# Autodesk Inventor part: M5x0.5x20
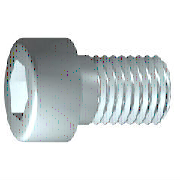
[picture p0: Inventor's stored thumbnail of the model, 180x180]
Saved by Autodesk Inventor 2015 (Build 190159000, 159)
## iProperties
IsCustomPart: 0
Created: 2009-02
Part Number: M5x0.5x20
Material: Steel, Mild
Description: 6각머리 태핑 나사
Document SubType Name: Modeling
Standard: KS B 1003
Designer: SeoGD™
Standards Organization: KS
Language: ko-KR
Size Designation: M 5 x 20
Categories: <MemberInstance><Categories><Category DisplayName="조임쇠" InternalName="e4da775c-781d-43d5-af7c-5136215cf5a6" Mnemonic="FSTN"><Category DisplayName="볼트" InternalN
Density: 7.86 g/cm^3
Appearance: Metal-Steel
Mass: 4.9629 g
Surface Area: 5.88237 cm^2
Volume: 0.631412 cm^3
Author: SeoGD™
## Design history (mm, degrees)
sketch "스케치1"
  geometry: L1 (-1.167, 0)-(20, 0); L2 (20, 0)-(20, 2.5); L3 (20, 2.5)-(2, 2.5); L4 (2, 2.5)-(1.509, 2.5); L5 (1.509, 2.5)-(0, 2.5); L6 (0, 2.5)-(0, 4.25); L7 (0, 4.25)-(-5, 4.25); L8 (-5, 4.25)-(-5, 2.309); L9 (-5, 2.309)-(-2.5, 2.309); L10 (-2.5, 2.309)-(-1.167, 0); L11 (-10, 0)-(25, 0) reference; L12 (0, -0.85)-(0, 5.1) reference; L13 (2, 2.5)-(0, 2.5)
  constraints: 22 end point, 6 parallel, 2 collinear, 2 perpendicular, 1 horizontal, 1 point on line
  dimensions: "d1" = 18 distance from line of L3.end L2 (= GEL); "d2" = 0.49086 distance of L4.end L3.end (computed from GAL); "d3" = 5 distance between parallel lines of L8 L6 (= KOH); "d4" = 2.5 distance of L8.end L9.end (= INTI); "d5" = 60 deg angle of L10 L1; "d6" = 5 diameter of L3 L1 (= GD); "d7" = 5 diameter of L5 L1 (= BDM); "d8" = 4.6188 diameter of L9 L1 (= 1.1547 x SW); "d9" = 8.5 diameter of L7 L1 (= KOD); "d26" = 20 distance between parallel lines of L12 L2 (= NLG)
revolve "본체" sketch "스케치1" stored, may be unused: angle "d10" = 90 deg
sketch "스케치2"
  geometry: L1 (0, -5.95)-(0, 5.95) reference; L2 (-5.95, 0)-(5.95, 0) reference; L3 (2.309, 0)-(1.155, -2); L4 (1.155, -2)-(-1.155, -2); L5 (-1.155, -2)-(-2.309, 0); L6 (-2.309, 0)-(-1.155, 2); L7 (-1.155, 2)-(1.155, 2); L8 (1.155, 2)-(2.309, 0); 2 further points
  constraints: 12 end point, 1 coincident, 1 horizontal alignment, 1 point on line, 12 other
extrude "슬롯" join sketch "스케치2" stored distance "d11" = 10; taper "d12" = 0 deg
workplane "Work Plane1"
fillet "Fillet2" dims "d30" = 0.1 (= R)
body "Solid1"
fillet "모깎기1" dims "d17" = 0.5 (= RR)
feature "스레드" dims "d13" = 18 (= GEL), "d14" = 0
chamfer "모따기1" distance "d15" = 0.49076 (= -0.5 x SPD + 0.5 x GD); stored, may be unused: second distance "d16" = 0.49076 (= GUL), angle "d27" = 45 deg
other parameters: "GD" = 5 (= NND) [user parameter; used in 2 equation terms], "NLG" = 20 [user parameter; used in 1 equation term], "GEL" = 18 [user parameter; used in 2 equation terms], "KOD" = 8.5 [user parameter; used in 1 equation term], "KOH" = 5 [user parameter; used in 1 equation term], "INTI" = 2.5 [user parameter; used in 1 equation term], "GAL" = 0.49076 (= 0.61345 x PTC) [user parameter; used in 1 equation term], "GUL" = 0.49076 (= 0.61345 x PTC) [user parameter; used in 1 equation term], "BDM" = 5 (= NND) [user parameter; used in 1 equation term], "SW" = 4 [user parameter; used in 2 equation terms], "RR" = 0.5 [user parameter; used in 1 equation term], "SPD" = 4.01848 (= NND - 1.2269 x PTC) [user parameter; used in 1 equation term], "d19" = 0, "d28" = 0, "d29" = 0, "R" = 0.1 [user parameter; used in 1 equation term], "PHH" = 0.2 [user parameter], "GD1" = 4.01848 (= THREADDIA - 1.2269 x PTC) [user parameter], "THREADDIA" = 5 [user parameter; used in 1 equation term], "FAWI" = 45 deg [user parameter], "TPU" = 12.5 (computed from PTC) [user parameter], "PTC" = 0.8 [user parameter; used in 5 equation terms], "NND" = 5 [user parameter; used in 3 equation terms], "TOA" = 30 deg [user parameter], "E0" = 4.62 (= 1.155 x SW) [user parameter]
